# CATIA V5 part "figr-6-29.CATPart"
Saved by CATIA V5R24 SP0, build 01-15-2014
Part number: Part1
Bounding box of the stored display mesh (mm): x -61 to 61, y 0 to 173.636, z 0 to 130.49
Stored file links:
  D:\KAVITA\CATIA V5-6R2014 Project_ Kavita\CATIA V5-6R2014_partfiles\Partfiles\c06_catia_v5-6r2014_prt\figr-6-29.CATPart
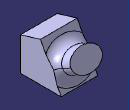
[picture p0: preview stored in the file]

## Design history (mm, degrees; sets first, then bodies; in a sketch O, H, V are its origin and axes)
Body1 (main body)
  Sketch1 on yz-plane, origin (0, 0, 0), H (0, 1, 0), V (0, 0, 1)
    line L1 (0, 0) -> (0, 110.5903)
    line L2 (0, 110.5903) -> (66.2814, 130.4899)
    line L3 (66.2814, 130.4899) -> (135.1646, 0)
    point P3 (135.1646, 0)
    line L4 (135.1646, 0) -> (0, 0)
    vertical: L1 V
    coincidence: P3 H
    horizontal: L4 H
  Pad1: profile Sketch1, direction (1, 0, 0), length 61, mirrored extent
  Sketch2 on face of Pad1, origin (0, 105.7081, 55.8014), H (-1, 0, 0), V (0, -0.4668, 0.8843)
    point P1 (0, 4.9672)
    ellipse A1 centre (0, 4.9672) semi-axes 50.9663, 34.9201 rotation 0
    coincidence: P1 V
  Pad2: profile Sketch2, direction (0, 0.8843, 0.4668), length 61
  Fillet1: radius 29, on edge [face of Pad1 | face of Pad2]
